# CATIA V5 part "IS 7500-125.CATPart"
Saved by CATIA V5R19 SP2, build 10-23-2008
Part number: IS 7500-125
Bounding box of the stored display mesh (mm): x -74.81 to 74.81, y -74.81 to 74.81, z 0 to 405
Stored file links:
  C:\Users\Bora\Desktop\3D Katı model\IS serisi\IS 7500\IS 7500-125.CATPart
  C:\Program Files\Dassault Systemes\B19\intel_a\reffiles\standard\MetricThickPitch.txt
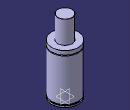
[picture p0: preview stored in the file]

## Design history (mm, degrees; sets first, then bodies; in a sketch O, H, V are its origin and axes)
Body1 (main body)
  Sketch1 on yz-plane, origin (0, 0, 0), H (0, 1, 0), V (0, 0, 1)
    point P1 (75, 255)
    point P2 (75, 250)
    point P5 (40, 404)
    point P7 (40, 404)
    point P12 (75, 250)
    point P13 (75, 255)
    arc A1 centre (75, 252.5) radius 2.5 from (75, 255) to (75, 250) ccw
    line L1 (75, 0) -> (75, 8)
    line L2 (40, 404) -> (40, 277)
    arc A2 centre (39, 404) radius 1 from (40, 404) to (39, 405) ccw
    line L3 (71, 15) -> (71, 8)
    line L4 (75, 15) -> (75, 250)
    line L5 (75, 255) -> (75, 277)
    line L6 (39, 405) -> (0, 405)
    point P15 (0, 405)
    line L7 (40, 277) -> (75, 277)
    line L8 (0, 0) -> (75, 0)
    line L9 (71, 15) -> (75, 15)
    line L10 (71, 8) -> (75, 8)
    coincidence: P15 V, P1 P13, P2 P12, P5 P7
    tangency: L6 A2
    horizontal: L7 H, L8 H, L9 H, L10 H
  Shaft1: profile Sketch1, axis Sketch1.V, angle 360
  Sketch2 on face of Shaft1 from Sketch1.L8, origin (0, 0, 0), H (1, 0, 0), V (0, -1, 0)
    point P1 (50, 0)
    distance P1 V = 50
  Hole1: placed by Sketch2, at (50, 0, 0) direction (0, 0, 1), diameter 8.376, depth 16, threaded "M10", thread diameter 10, thread depth 16, pitch 1.5
  CircPattern1: of Hole1, instances 4, angular step 90, axis from xy-plane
